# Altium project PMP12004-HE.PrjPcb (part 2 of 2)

## Sheet PMP12004-HE_sh6.SchDoc: VCCINT Core Rail
size 431 x 279 mm; Date: Not shown in title block; ApprovedBy: Not shown in title block; CheckedBy: Not shown in title block; Author: Not shown in title block; CompanyName: Not shown in title block; Engineer: Not shown in title block; Organization: Not shown in title block; Address1: Not shown in title block; Address2: Not shown in title block; Address3: Not shown in title block; Address4: Not shown in title block; DocumentNumber: 6; Revision: Use project parameter SCH_Rev; SheetNumber: 6; SheetTotal: 7; PageSetup: Record=PageOptions¦CenterHorizontal=True¦CenterVertical=True¦PrintScale=0.64¦XCorrection=1.00¦YCorrection=1.00¦PrintKind=0¦BorderSize=5000000¦LeftOffset=0¦BottomOffset=0¦Orientation=2¦PaperLength=1000¦PaperWidth=1000¦Scale=100¦PaperSource=15¦PrintQuality=600¦MediaType=1¦DitherType=10¦PrintScaleMode=1¦PaperKind=Letter
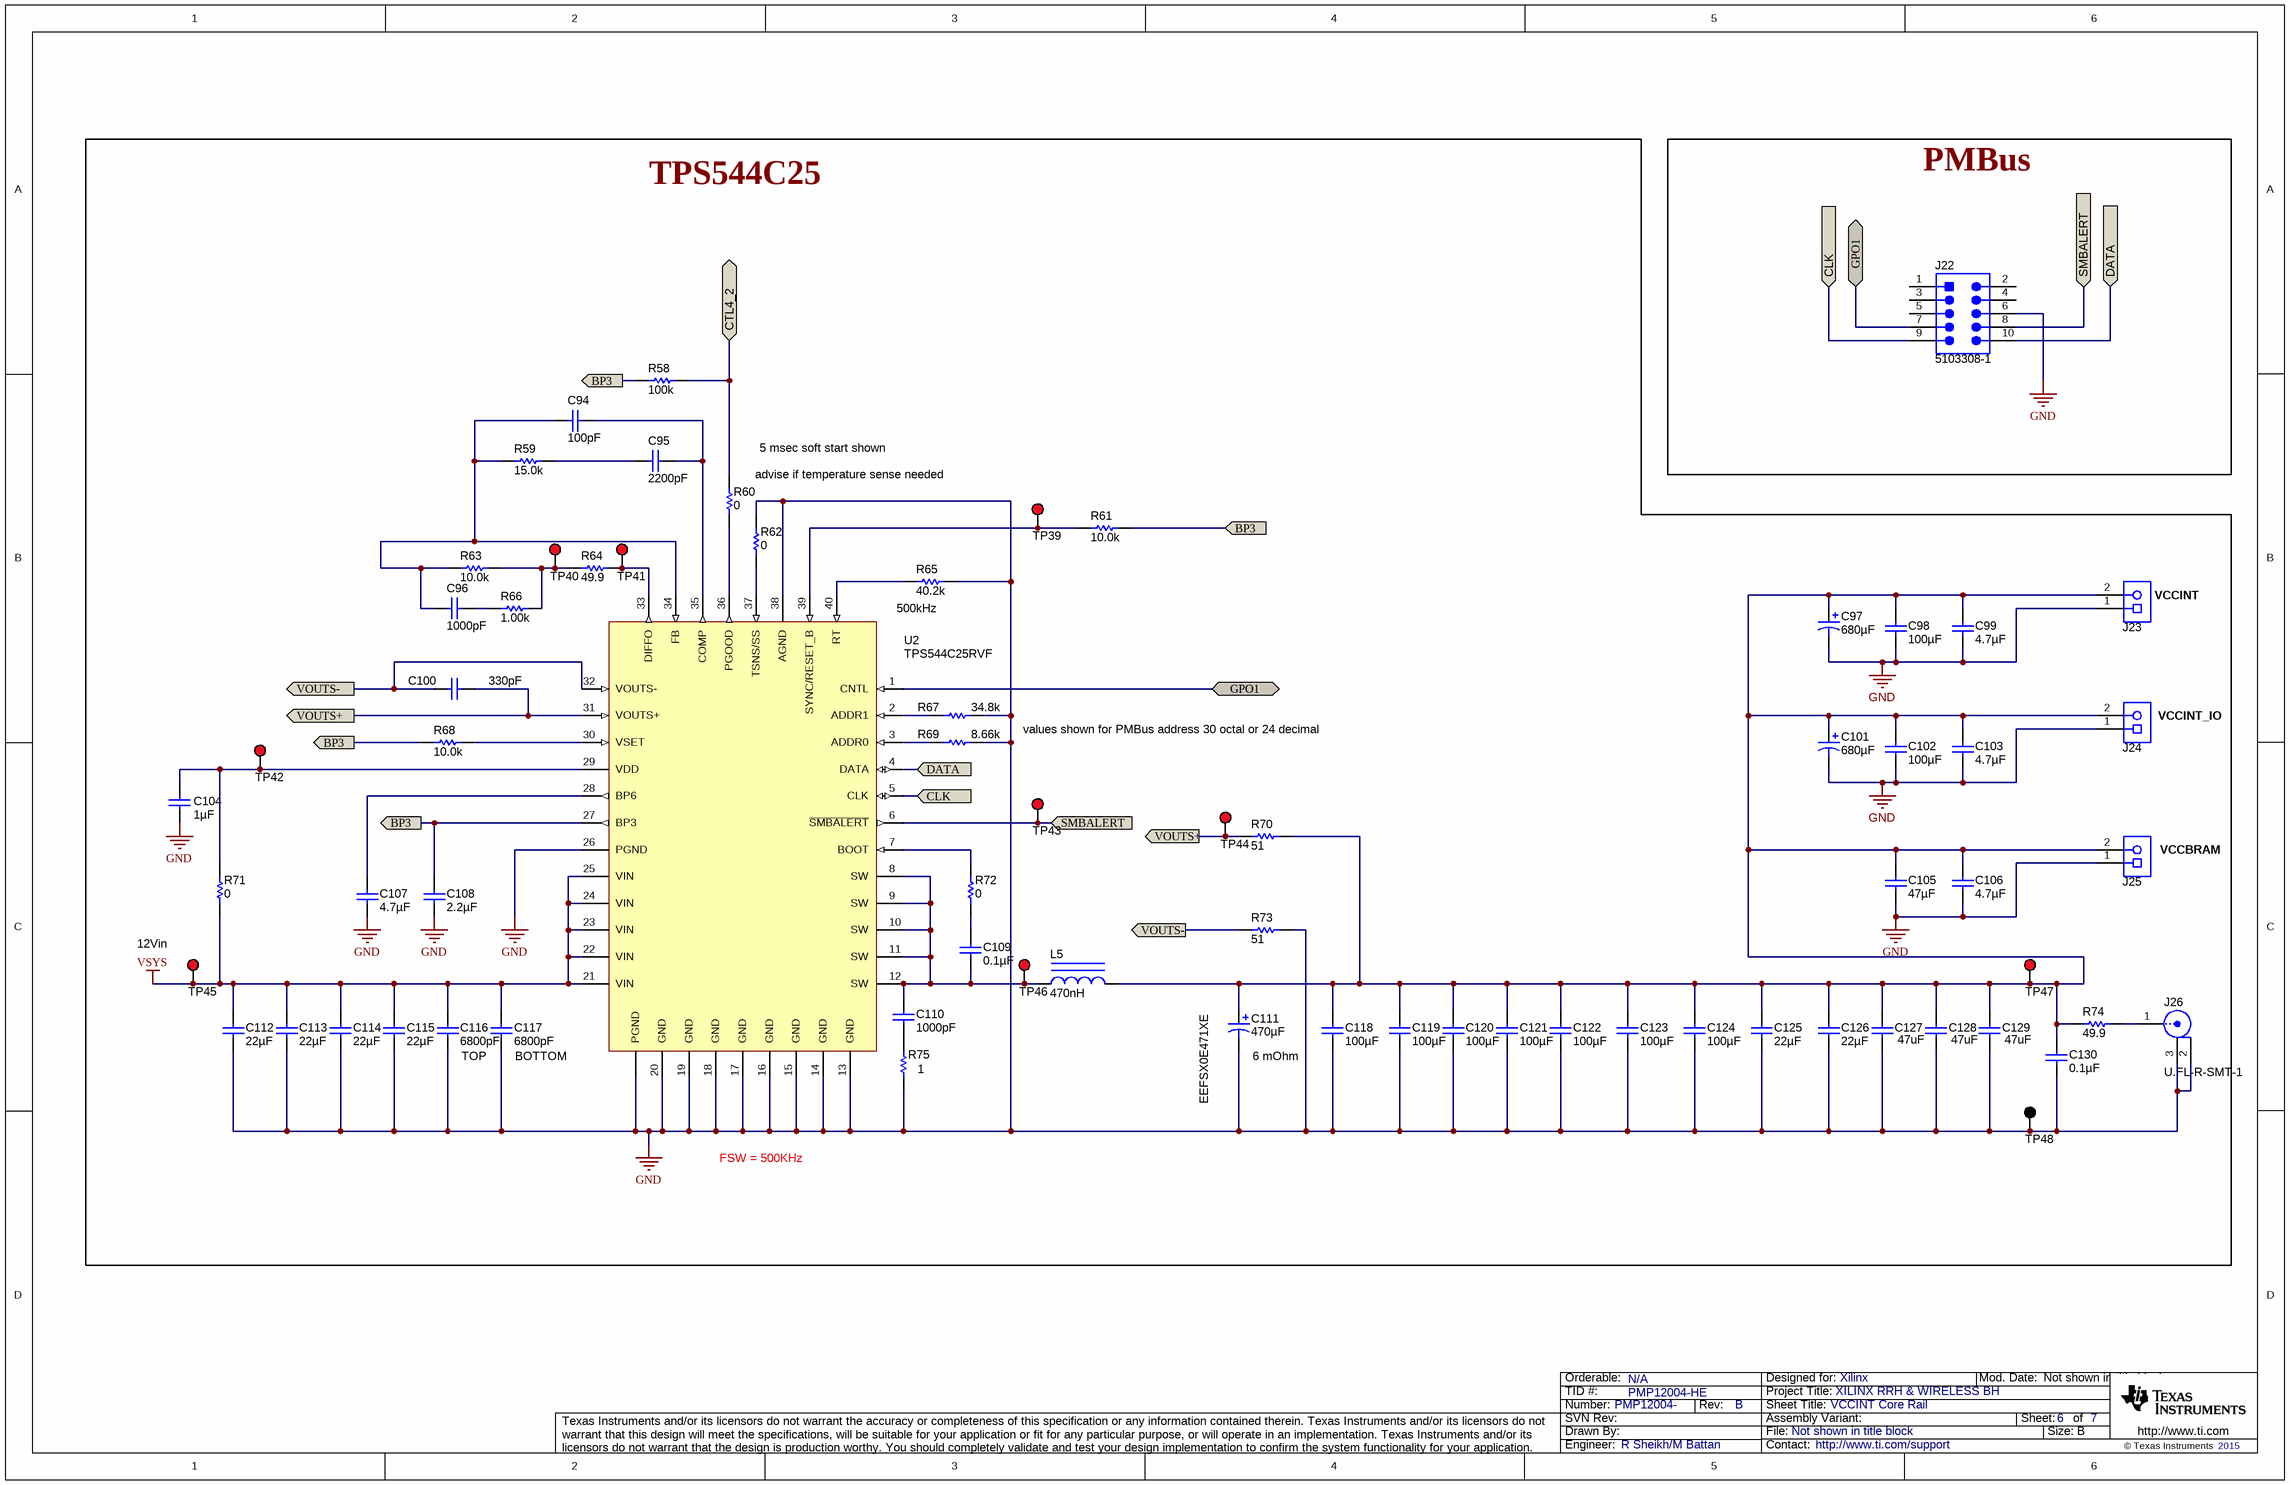
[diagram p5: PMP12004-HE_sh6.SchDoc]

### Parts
C94  ValueDisplayed: 100pF  [0402]  (hidden comment: GRM1535C1H101JDD5D)
C95  ValueDisplayed: 2200pF  [0402]  (hidden comment: C1005X7R1H222K)
C96  ValueDisplayed: 1000pF  [0402]  (hidden comment: GRM155R71H102KA01D)
C97  ValueDisplayed: 680µF  [SM_RADIAL_10AMM]  (hidden comment: 4SVP680M)
C98  ValueDisplayed: 100µF  [0805_HV]  (hidden comment: GRM21BR60G107ME15L)
C99  ValueDisplayed: 4.7µF  [0603]  (hidden comment: GRM188R60J475ME19D)
C100  ValueDisplayed: 330pF  [0402]  (hidden comment: GRM155R71H331KA01D)
C101  ValueDisplayed: 680µF  [SM_RADIAL_10AMM]  (hidden comment: 4SVP680M)
C102  ValueDisplayed: 100µF  [0805_HV]  (hidden comment: GRM21BR60G107ME15L)
C103  ValueDisplayed: 4.7µF  [0603]  (hidden comment: GRM188R60J475ME19D)
C104  ValueDisplayed: 1µF  [0603L]  (hidden comment: GRM188R71E105KA12D)
C105  ValueDisplayed: 47µF  [0603]  (hidden comment: GRM188R60J476M)
C106  ValueDisplayed: 4.7µF  [0603]  (hidden comment: GRM188R60J475KE19D)
C107  ValueDisplayed: 4.7µF  [0603]  (hidden comment: GRM185C81A475ME11D)
C108  ValueDisplayed: 2.2µF  [0402L]  (hidden comment: GRM155C80J225KE95D)
C109  ValueDisplayed: 0.1µF  [0402]  (hidden comment: C1005X7R1H104M)
C110  ValueDisplayed: 1000pF  [0603]  (hidden comment: 06031C102JAT2A)
C111  ValueDisplayed: 470µF  Value1: 6 mOhm  [SP-Cap_Standard]  (hidden comment: EEFSX0E471XE)
C112  ValueDisplayed: 22µF  [1210]  (hidden comment: GRM32EC81E226KE15L)
C113  ValueDisplayed: 22µF  [1210]  (hidden comment: GRM32EC81E226KE15L)
C114  ValueDisplayed: 22µF  [1210]  (hidden comment: GRM32EC81E226KE15L)
C115  ValueDisplayed: 22µF  [1210]  (hidden comment: GRM32EC81E226KE15L)
C116  ValueDisplayed: 6800pF  Placement: TOP  [0402]  (hidden comment: GRM155R71E682KA01D)
C117  ValueDisplayed: 6800pF  Placement: BOTTOM  [0402]  (hidden comment: GRM155R71E682KA01D)
C118  ValueDisplayed: 100µF  [1210]  (hidden comment: GRM32EC80J107ME20L)
C119  ValueDisplayed: 100µF  [1210]  (hidden comment: GRM32EC80J107ME20L)
C120  ValueDisplayed: 100µF  [1210]  (hidden comment: GRM32EC80J107ME20L)
C121  ValueDisplayed: 100µF  [1210]  (hidden comment: GRM32EC80J107ME20L)
C122  ValueDisplayed: 100µF  [1210]  (hidden comment: GRM32EC80J107ME20L)
C123  ValueDisplayed: 100µF  [1210]  (hidden comment: GRM32EC80J107ME20L)
C124  ValueDisplayed: 100µF  [1210]  (hidden comment: GRM32EC80J107ME20L)
C125  ValueDisplayed: 22µF  [0805_HV]  (hidden comment: GRM21BC80G226ME39L)
C126  ValueDisplayed: 22µF  [0805_HV]  (hidden comment: GRM21BC80G226ME39L)
C127  value 47uF  [0805_HV]  (hidden comment: GRM21BR61A476ME15)
C128  value 47uF  [0805_HV]  (hidden comment: GRM21BR61A476ME15)
C129  value 47uF  [0805_HV]  (hidden comment: GRM21BR61A476ME15)
C130  ValueDisplayed: 0.1µF  [0402]  (hidden comment: GRM155R61E104KA87D)
J22  5103308-1  [CONN_5103308-1]
J23  1935776  [Phoenix_1935776]  (value not drawn)
J24  1935776  [Phoenix_1935776]  (value not drawn)
J25  1935776  [Phoenix_1935776]  (value not drawn)
J26  U.FL-R-SMT-1  [CONN_UFL-R-SMT-1]
L5  ValueDisplayed: 470nH  [WE-HCM_1390]  (hidden comment: 744309047)
R58  ValueDisplayed: 100k  [0402]  (hidden comment: CRCW0402100KFKED)
R59  ValueDisplayed: 15.0k  [0402]  (hidden comment: CRCW040215K0FKED)
R60  ValueDisplayed: 0  [0402]  (hidden comment: CRCW04020000Z0ED)
R61  ValueDisplayed: 10.0k  [0402]  (hidden comment: CRCW040210K0FKED)
R62  ValueDisplayed: 0  [0402]  (hidden comment: CRCW04020000Z0ED)
R63  ValueDisplayed: 10.0k  [0402]  (hidden comment: CRCW040210K0FKED)
R64  ValueDisplayed: 49.9  [0402]  (hidden comment: ERJ-2RKF49R9X)
R65  ValueDisplayed: 40.2k  [0402]  (hidden comment: CRCW040240K2FKED)
R66  ValueDisplayed: 1.00k  [0402]  (hidden comment: CRCW04021K00FKED)
R67  ValueDisplayed: 34.8k  [0402]  (hidden comment: CRCW040234K8FKED)
R68  ValueDisplayed: 10.0k  [0402]  (hidden comment: CRCW040210K0FKED)
R69  ValueDisplayed: 8.66k  [0402]  (hidden comment: CRCW04028K66FKED)
R70  ValueDisplayed: 51  [0402]  (hidden comment: CRCW040251R0JNED)
R71  ValueDisplayed: 0  [0402]  (hidden comment: CRCW04020000Z0ED)
R72  ValueDisplayed: 0  [0402]  (hidden comment: CRCW04020000Z0ED)
R73  ValueDisplayed: 51  [0402]  (hidden comment: CRCW040251R0JNED)
R74  ValueDisplayed: 49.9  [0402]  (hidden comment: CRCW040249R9FKED)
R75  value 1  [1206]  (hidden comment: CRCW12061R00JNEA)
TP39  5000  [Keystone5000]  (value not drawn)
TP40  5000  [Keystone5000]  (value not drawn)
TP41  5000  [Keystone5000]  (value not drawn)
TP42  5000  [Keystone5000]  (value not drawn)
TP43  5000  [Keystone5000]  (value not drawn)
TP44  5000  [Keystone5000]  (value not drawn)
TP45  5000  [Keystone5000]  (value not drawn)
TP46  5000  [Keystone5000]  (value not drawn)
TP47  5000  [Keystone5000]  (value not drawn)
TP48  5001  [Keystone5001]  (value not drawn)
U2  TPS544C25RVF  [RVF0040A]

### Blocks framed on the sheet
TPS544C25: C94-C130 J23-J26 L5 R58-R75 TP39-TP48 U2
PMBus: J22

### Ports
BP3, CLK, CTL4_2 (bidir), DATA, GPO1 (bidir), SMBALERT, VOUTS+, VOUTS-

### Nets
GND: C97.2(-) C98.2 C99.2 C101.2(-) C102.2 C103.2 C104.2 C105.2 C106.2 C107.2 C108.2 C111.2(-) C112.2 C113.2 C114.2 C115.2 C116.2 C117.2 C118.2 C119.2 C120.2 C121.2 C122.2 C123.2 C124.2 C125.2 C126.2 C127.2 C128.2 C129.2 C130.2 J22.6 J23.1 J24.1 J25.1 J26.2 J26.3 R62.2 R65.2 R67.2 R69.2 R73.2 R75.1 TP48.1 U2.13(GND) U2.14(GND) U2.15(GND) U2.16(GND) U2.17(GND) U2.18(GND) U2.19(GND) U2.20(GND) U2.26(PGND) U2.38(AGND) U2.41(PGND)
VSYS: C112.1 C113.1 C114.1 C115.1 C116.1 C117.1 R71.1 TP45.1 U2.21(VIN) U2.22(VIN) U2.23(VIN) U2.24(VIN) U2.25(VIN)
BP3: C108.1 R58.1 R61.2 R68.1 U2.27(BP3) ; port BP3
CLK: J22.9 U2.5(CLK) ; port CLK
CTL4_2: R58.2 R60.1 ; port CTL4_2
DATA: J22.10 U2.4(DATA) ; port DATA
GPO1: J22.7 U2.1(CNTL) ; port GPO1
SMBALERT: J22.8 TP43.1 U2.6(~{SMBALERT}) ; port SMBALERT
VOUTS+: C100.1 R70.1 TP44.1 U2.31(VOUTS+) ; port VOUTS+
VOUTS-: C100.2 R73.1 U2.32(VOUTS-) ; port VOUTS-
NetC94_1: C94.1 C96.2 R59.1 R63.2 U2.34(FB)
NetC94_2: C94.2 C95.1 U2.35(COMP)
NetC95_2: C95.2 R59.2
NetC96_1: C96.1 R66.1
NetC97_1: C97.1(+) C98.1 C99.1 C101.1(+) C102.1 C103.1 C105.1 C106.1 C111.1(+) C118.1 C119.1 C120.1 C121.1 C122.1 C123.1 C124.1 C125.1 C126.1 C127.1 C128.1 C129.1 C130.1 J23.2 J24.2 J25.2 L5.2 R70.2 R74.1 TP47.1
NetC104_1: C104.1 R71.2 TP42.1 U2.29(VDD)
NetC107_1: C107.1 U2.28(BP6)
NetC109_1: C109.1 R72.1
NetC109_2: C109.2 C110.1 L5.1 TP46.1 U2.8(SW) U2.9(SW) U2.10(SW) U2.11(SW) U2.12(SW)
NetC110_2: C110.2 R75.2
NetJ26_1: J26.1 R74.2
NetR60_2: R60.2 U2.36(PGOOD)
NetR61_1: R61.1 TP39.1 U2.39(SYNC/RESET_B)
NetR62_1: R62.1 U2.37(TSNS/SS)
NetR63_1: R63.1 R64.1 R66.2 TP40.1
NetR64_2: R64.2 TP41.1 U2.33(DIFFO)
NetR65_1: R65.1 U2.40(RT)
NetR67_1: R67.1 U2.2(ADDR1)
NetR68_2: R68.2 U2.30(VSET)
NetR69_1: R69.1 U2.3(ADDR0)
NetR72_2: R72.2 U2.7(BOOT)

Not connected (* = marked no-connect by the designer): J22 1 2 3 4 5

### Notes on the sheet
- (near R60) 5 msec soft start shown
- (near R60) advise if temperature sense needed
- 500kHz
- (near J23) VCCINT
- values shown for PMBus address 30 octal or 24 decimal
- (near J24) VCCINT_IO
- (near J25) VCCBRAM
- (near TP45) 12Vin
- FSW = 500KHz

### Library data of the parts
C94 = GRM1535C1H101JDD5D: CAP, CERM, 100 pF, 50 V, +/- 5%, C0G/NP0, 0402; Manufacturer: MuRata; Polarized: N; CompType: Capacitor; Value: 100pF; U/M: EA; Cap_F: 0.0000000001; Tolerance_%: 5; Value1: Unknown; VDC_V: 50; Value2: 50V; TaMin_C: -55; TaMax_C: 125; AEC Category: Q200
C95 = C1005X7R1H222K: CAP, CERM, 2200 pF, 50 V, +/- 10%, X7R, 0402; Manufacturer: TDK; Polarized: N; CompType: Capacitor; Value: 2200pF; U/M: EA; Cap_F: 0.0000000022; Tolerance_%: 10; ESR_ohm: 0.1433; Value1: 0.1433 ohm; VDC_V: 50; Value2: 50V; TaMin_C: -55; TaMax_C: 125; AEC Category: Q200
C96 = GRM155R71H102KA01D: CAP, CERM, 1000 pF, 50 V, +/- 10%, X7R, 0402; Manufacturer: MuRata; Polarized: N; CompType: Capacitor; Value: 1000pF; U/M: EA; Cap_F: 0.000000001; Tolerance_%: 10; Value1: Unknown; VDC_V: 50; Value2: 50V; TaMin_C: -55; TaMax_C: 125; AEC Category: Q200
C97 C101 = 4SVP680M: CAP, Aluminum Polymer, 680 µF, 4 V, +/- 20%, 0.025 ohm, 10x10.3 SMD; Manufacturer: Panasonic; Polarized: Y; CompType: Capacitor; Value: 680uF; U/M: EA; Cap_F: 0.00068; Tolerance_%: 20; VDC_V: 4; Value2: 4V; ESR_ohm: 0.025; IRMS_A: 3.7; TaMin_C: -55; TaMax_C: 105; Cap_Case: 10.3x10.3x7.9; AEC Category: Q200
C98 C102 = GRM21BR60G107ME15L: CAP, CERM, 100 µF, 4 V, +/- 20%, X5R, 0805; Manufacturer: MuRata; Polarized: N; CompType: Capacitor; Value: 100uF; U/M: EA; Cap_F: 0.0001; Tolerance_%: 20; Value1: Unknown; VDC_V: 4; Value2: 4V; TaMin_C: -55; TaMax_C: 85; Cap_Case: 0805; AEC Category: Q200
C99 C103 = GRM188R60J475ME19D: CAP, CERM, 4.7 µF, 6.3 V, +/- 20%, X5R, 0603; Manufacturer: MuRata; Polarized: N; CompType: Capacitor; Value: 4.7uF; U/M: EA; Cap_F: 0.0000047; Tolerance_%: 20; ESR_ohm: 0.001; Value1: 0.001 ohm; VDC_V: 6.3; Value2: 6.3V; TaMin_C: -55; TaMax_C: 125; AEC Category: Q200
C100 = GRM155R71H331KA01D: CAP, CERM, 330 pF, 50 V, +/- 10%, X7R, 0402; Manufacturer: MuRata; Polarized: N; CompType: Capacitor; Value: 330pF; U/M: EA; Cap_F: 0.00000000033; Tolerance_%: 10; Value1: Unknown; VDC_V: 50; Value2: 50V; TaMin_C: -55; TaMax_C: 125
C104 = GRM188R71E105KA12D: CAP, CERM, 1uF, 25V, +/-10%, X7R, 0603; Manufacturer: MuRata; Polarized: N; CompType: Capacitor; U/M: EA; Cap_F: 0.000001; Tolerance_%: 10; Value1: Unknown; VDC_V: 25; TaMin_C: -55; TaMax_C: 125; Cap_Case: 0603
C105 = GRM188R60J476M: CAP, CERM, 47 µF, 6.3 V, +/- 20%, X5R, 0603; Manufacturer: MuRata; Polarized: N; CompType: Capacitor; Value: 47uF; U/M: EA; Cap_F: 0.000047; Tolerance_%: 20; Value1: Unknown; VDC_V: 6.3; Value2: 6.3V; TaMin_C: -55; TaMax_C: 85; AEC Category: Q200
C106 = GRM188R60J475KE19D: CAP, CERM, 4.7 µF, 6.3 V, +/- 10%, X5R, 0603; Manufacturer: MuRata; Polarized: N; CompType: Capacitor; Value: 4.7uF; U/M: EA; Cap_F: 0.0000047; Tolerance_%: 10; ESR_ohm: 0.005; Value1: 0.005 ohm; VDC_V: 6.3; Value2: 6.3V; IRMS_A: 2; TaMin_C: -55; TaMax_C: 85; AEC Category: Q200
C107 = GRM185C81A475ME11D: CAP, CERM, 4.7 µF, 10 V, +/- 20%, X6S, 0603; Manufacturer: MuRata; Polarized: N; CompType: Capacitor; Value: 4.7uF; U/M: EA; Cap_F: 0.0000047; Tolerance_%: 20; Value1: Unknown; VDC_V: 10; Value2: 10V; TaMin_C: -55; TaMax_C: 105
C108 = GRM155C80J225KE95D: CAP, CERM, 2.2 µF, 6.3 V, +/- 10%, X6S, 0402; Manufacturer: MuRata; Polarized: N; CompType: Capacitor; Value: 2.2uF; U/M: EA; Cap_F: 0.0000022; Tolerance_%: 10; Value1: Unknown; VDC_V: 6.3; Value2: 6.3V; TaMin_C: -55; TaMax_C: 105; Cap_Case: 0402
C109 = C1005X7R1H104M: CAP, CERM, 0.1 µF, 50 V, +/- 20%, X7R, 0402; Manufacturer: TDK; Polarized: N; CompType: Capacitor; Value: 0.1uF; U/M: EA; Cap_F: 0.0000001; Tolerance_%: 20; Value1: Unknown; VDC_V: 50; Value2: 50V; TaMin_C: -55; TaMax_C: 125
C110 = 06031C102JAT2A: CAP, CERM, 1000pF, 100V, +/-5%, X7R, 0603; Manufacturer: AVX; Polarized: N; CompType: Capacitor; U/M: EA; Cap_F: 0.000000001; Tolerance_%: 5; ESR_Ohm: 0.276; Value1: 0.276 ohm; VDC_V: 100; TaMin_C: -55; TaMax_C: 125
C111 = EEFSX0E471ER: CAP, Aluminum Polymer, 470 µF, 2.5 V, +/- 20%, 9 ohm, 7.3x1.8x4.3mm SMD; Manufacturer: Panasonic; Polarized: Y; CompType: Capacitor; Value: 470uF; U/M: EA; Cap_F: 0.00047; Tolerance_%: 20; VDC_V: 2.5; Value2: 2.5V; ESR_ohm: 9; IRMS_A: 3; TaMin_C: -40; TaMax_C: 105
C112-C115 = GRM32EC81E226KE15L: CAP, CERM, 22uF, 25V, +/-10%, X6S, 1210; Manufacturer: MuRata; Polarized: N; CompType: Capacitor; U/M: EA; Cap_F: 0.000022; Tolerance_%: 10; Value1: Unknown; VDC_V: 25; TaMin_C: -55; TaMax_C: 105
C116 C117 = GRM155R71E682KA01D: CAP, CERM, 6800pF, 25V, +/-10%, X7R, 0402; Manufacturer: MuRata; Polarized: N; CompType: Capacitor; U/M: EA; Cap_F: 0.0000000068; Tolerance_%: 10; Value1: Unknown; VDC_V: 25; TaMin_C: -55; TaMax_C: 125
C118-C124 = GRM32EC80J107ME20L: CAP, CERM, 100 µF, 6.3 V, +/- 20%, X6S, 1210; Manufacturer: MuRata; Polarized: N; CompType: Capacitor; Value: 100uF; U/M: EA; Cap_F: 0.0001; Tolerance_%: 20; Value1: Unknown; VDC_V: 6.3; Value2: 6.3V; TaMin_C: -55; TaMax_C: 105
C125 C126 = GRM21BC80G226ME39L: CAP, CERM, 22 µF, 4 V, +/- 20%, X6S, 0805; Manufacturer: MuRata; Polarized: N; CompType: Capacitor; Value: 22uF; U/M: EA; Cap_F: 0.000022; Tolerance_%: 20; Value1: Unknown; VDC_V: 4; Value2: 4V; TaMin_C: -55; TaMax_C: 105; Cap_Case: 0805
C127-C129 = GRM21BR61A476ME15: CAP, CERM, 47 µF, 10 V, +/- 20%, X5R, 0805; Manufacturer: MuRata; Polarized: N; CompType: Capacitor; ValueDisplayed: DNP; U/M: EA; Cap_F: 0.000047; Tolerance_%: 20; Value1: Unknown; VDC_V: 10; Value2: 10V; TaMin_C: -55; TaMax_C: 85; Cap_Case: 0805; AEC Category: Q200
C130 = GRM155R61E104KA87D: CAP, CERM, 0.1 µF, 25 V, +/- 10%, X5R, 0402; Manufacturer: MuRata; Polarized: N; CompType: Capacitor; Value: 0.1uF; U/M: EA; Cap_F: 0.0000001; Tolerance_%: 10; Value1: Unknown; VDC_V: 25; Value2: 25V; TaMin_C: -55; TaMax_C: 85
J22 = 5103308-1: Header (shrouded), 100mil, 5x2, Gold, TH; Manufacturer: TE Connectivity; SymbolCreator: a0412235; U/M: EA
J23-J25 = 1935776: Terminal Block, 2x1, 5mm, Green, TH; Manufacturer: Phoenix Contact; SymbolCreator: a0412235; U/M: EA
J26 = U.FL-R-SMT-1: Connector, Ultra-Mini Coaxial, SMD; Manufacturer: Hirose Electric Co. Ltd.; SymbolCreator: a0412235; U/M: EA
L5 = 744309047: Inductor, Shielded Drum Core, Ferrite, 470 nH, 40.5 A, 0.000165 ohm, SMD; Manufacturer: Wurth Elektronik; Value: 470nH; Ind_H: 470.0E-9; Imax_A: 40.5; Irms: 47.5A @ 40C rise; Isat: 40.5A @ 20% inductance drop; Value2: 40.5A; AEC Category: Q200
R58 = CRCW0402100KFKED: RES, 100 k, 1%, 0.063 W, 0402; Manufacturer: Vishay-Dale; CompType: Resistor; Value: 100k; Res_ohm: 100000; Tolerance_%: 1; Power_W: 0.063; Value2: 0.063W; VDC_V: 50; TempCo: 100 ppm/C; EIA_Code: E96; U/M: EA
R59 = CRCW040215K0FKED: RES, 15.0 k, 1%, 0.063 W, 0402; Manufacturer: Vishay-Dale; CompType: Resistor; Value: 15.0k; Res_ohm: 15000; Value_Code: 15k0; Tolerance_%: 1; Power_W: 0.063; Value2: 0.063W; VDC_V: 50; TempCo: 100 ppm/C; EIA_Code: E96; U/M: EA; AEC Category: Q200
R60 R62 R71 R72 = CRCW04020000Z0ED: RES, 0, 5%, 0.063 W, 0402; Manufacturer: Vishay-Dale; CompType: Resistor; Value: 0; Value_Code: 0000; Tolerance_%: 5; Power_W: 0.063; Value2: 0.063W; VDC_V: 50; TempCo: 200 ppm/C; EIA_Code: E24; U/M: EA
R61 R63 R68 = CRCW040210K0FKED: RES, 10.0 k, 1%, 0.063 W, 0402; Manufacturer: Vishay-Dale; CompType: Resistor; Value: 10.0k; Res_ohm: 10000; Value_Code: 10k0; Tolerance_%: 1; Power_W: 0.063; Value2: 0.063W; VDC_V: 50; TempCo: 100 ppm/C; EIA_Code: E96; U/M: EA
R64 = ERJ-2RKF49R9X: RES, 49.9, 1%, 0.1 W, AEC-Q200 Grade 0, 0402; Manufacturer: Panasonic; CompType: Resistor; Value: 49.9; Value_Code: 49R9; Tolerance_%: 1; Power_W: 0.1; Value2: 0.1W; VDC_V: 50; TempCo: 100 ppm/C; EIA_Code: E96; U/M: EA; AEC Category: Q200; AEC Qualified: Y; AEC Grade: 0
R65 = CRCW040240K2FKED: RES, 40.2 k, 1%, 0.063 W, 0402; Manufacturer: Vishay-Dale; CompType: Resistor; Value: 40.2k; Res_ohm: 40200; Value_Code: 40k2; Tolerance_%: 1; Power_W: 0.063; Value2: 0.063W; VDC_V: 50; TempCo: 100 ppm/C; EIA_Code: E96; U/M: EA
R66 = CRCW04021K00FKED: RES, 1.00 k, 1%, 0.063 W, 0402; Manufacturer: Vishay-Dale; CompType: Resistor; Value: 1.00k; Res_ohm: 1000; Value_Code: 1k00; Tolerance_%: 1; Power_W: 0.063; Value2: 0.063W; VDC_V: 50; TempCo: 100 ppm/C; EIA_Code: E96; U/M: EA
R67 = CRCW040234K8FKED: RES, 34.8 k, 1%, 0.063 W, 0402; Manufacturer: Vishay-Dale; CompType: Resistor; Value: 34.8k; Res_ohm: 34800; Value_Code: 34k8; Tolerance_%: 1; Power_W: 0.063; Value2: 0.063W; VDC_V: 50; TempCo: 100 ppm/C; EIA_Code: E96; U/M: EA
R69 = CRCW04028K66FKED: RES, 8.66 k, 1%, 0.063 W, 0402; Manufacturer: Vishay-Dale; CompType: Resistor; Value: 8.66k; Res_ohm: 8660; Value_Code: 8k66; Tolerance_%: 1; Power_W: 0.063; Value2: 0.063W; VDC_V: 50; TempCo: 100 ppm/C; EIA_Code: E96; U/M: EA
R70 R73 = CRCW040251R0JNED: RES, 51, 5%, 0.063 W, 0402; Manufacturer: Vishay-Dale; CompType: Resistor; Value: 51; Value_Code: 51R0; Tolerance_%: 5; Power_W: 0.063; Value2: 0.063W; VDC_V: 50; TempCo: 200 ppm/C; EIA_Code: E24; U/M: EA
R74 = CRCW040249R9FKED: RES, 49.9, 1%, 0.063 W, 0402; Manufacturer: Vishay-Dale; CompType: Resistor; Value: 49.9; Value_Code: 49R9; Tolerance_%: 1; Power_W: 0.063; Value2: 0.063W; VDC_V: 50; TempCo: 100 ppm/C; EIA_Code: E96; U/M: EA
R75 = CRCW12061R00JNEA: RES, 1.0 ohm, 5%, 0.25W, 1206; Manufacturer: Vishay-Dale; CompType: Resistor; Value_Code: 1R00; Tolerance_%: 5; Power_W: 0.25; VDC_V: 200; TempCo: 200 ppm/C; EIA_Code: E24; U/M: EA
TP39-TP47 = 5000: Test Point, Miniature, Red, TH; Manufacturer: Keystone; CompType: Test Point Loop; U/M: EA
TP48 = 5001: Test Point, Miniature, Black, TH; Manufacturer: Keystone; CompType: Test Point Loop; U/M: EA
U2 = TPS544C24RVF: 18V, 30A PMBUS SYNCHRONOUS BUCK CONVERTERS, RVF0040A; Alternate Manufacturer: None; Manufacturer: Texas Instruments; SymbolCreator: a0411947; CompType: IC; U/M: EA

## Sheet PMP12004-HE_Hardware.SchDoc
size 431 x 279 mm; Date: Not shown in title block; ApprovedBy: Not shown in title block; CheckedBy: Not shown in title block; Author: Not shown in title block; CompanyName: Not shown in title block; Engineer: Not shown in title block; Organization: Not shown in title block; Address1: Not shown in title block; Address2: Not shown in title block; Address3: Not shown in title block; Address4: Not shown in title block; DocumentNumber: 7; Revision: Use project parameter SCH_Rev; SheetNumber: 7; SheetTotal: 7; PageSetup: Record=PageOptions¦CenterHorizontal=True¦CenterVertical=True¦PrintScale=1.00¦XCorrection=1.00¦YCorrection=1.00¦PrintKind=0¦BorderSize=5000000¦LeftOffset=0¦BottomOffset=0¦Orientation=2¦PaperLength=1000¦PaperWidth=1000¦Scale=100¦PaperSource=15¦PrintQuality=600¦MediaType=1¦DitherType=10¦PaperKind=Letter¦PrintScaleMode=1
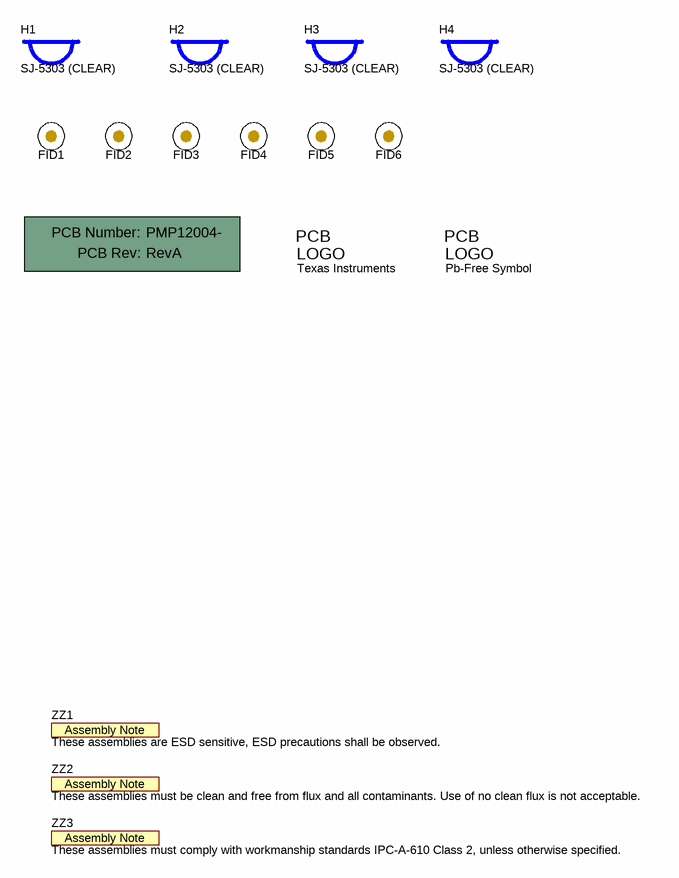
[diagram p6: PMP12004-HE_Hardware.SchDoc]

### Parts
!PCB1  Printed Circuit Board  (value not drawn)  (mechanical)
FID1  Fiducial  [Fiducial10-20]  (value not drawn)  (no BOM)
FID2  Fiducial  [Fiducial10-20]  (value not drawn)  (no BOM)
FID3  Fiducial  [Fiducial10-20]  (value not drawn)  (no BOM)
FID4  Fiducial  [Fiducial10-20]  (value not drawn)  (no BOM)
FID5  Fiducial  [Fiducial10-20]  (value not drawn)  (no BOM)
FID6  Fiducial  [Fiducial10-20]  (value not drawn)  (no BOM)
H1  SJ-5303 (CLEAR)  [Bumpon_SJ5003Transparent]
H2  SJ-5303 (CLEAR)  [Bumpon_SJ5003Transparent]
H3  SJ-5303 (CLEAR)  [Bumpon_SJ5003Transparent]
H4  SJ-5303 (CLEAR)  [Bumpon_SJ5003Transparent]
Logo1  Texas Instruments  [TI_Stacked_Overlay_Small]  (no BOM)
Logo2  Pb-Free Symbol  [Pb-Free_Overlay_Small]  (no BOM)
ZZ1  These assemblies are ESD sensitive, ESD precautions shall be observed.  [AssemblyNote]  (no BOM)
ZZ2  These assemblies must be clean and free from flux and all contaminants. Use of no clean flux is not acceptable.  [AssemblyNote]  (no BOM)
ZZ3  These assemblies must comply with workmanship standards IPC-A-610 Class 2, unless otherwise specified.  [AssemblyNote]  (no BOM)

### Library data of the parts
!PCB1 = PCB: Manufacturer: Any; PartNumber: PMP12004-; SymbolCreator: a0412235
FID1-FID6 = Fiducial: Fiducial mark.  There is nothing to buy or mount.; SymbolCreator: codlsc
H1-H4 = SJ-5303 (CLEAR): Bumpon, Hemisphere, 0.44 X 0.20, Clear; Manufacturer: 3M; SymbolCreator: a0412235
Logo1 = TI_Logo: Texas Instrument Corporate Signature; SymbolCreator: codlsc
Logo2 = Pb-Free: SymbolCreator: a0412235
ZZ1-ZZ3 = AssemblyNote: SymbolCreator: codlsc

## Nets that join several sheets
BUCK1_OUT: PMP12004-HE_sh1 (5 pins), PMP12004-HE_sh2 (16 pins)
BUCK5_OUT: PMP12004-HE_sh1 (R1.1 R3.1), PMP12004-HE_sh4 (19 pins)
BUCK6_OUT: PMP12004-HE_sh1 (R7.1), PMP12004-HE_sh4 (18 pins)
GND: PMP12004-HE_sh1 (31 pins), PMP12004-HE_sh2 (50 pins), PMP12004-HE_sh3 (60 pins), PMP12004-HE_sh4 (49 pins), PMP12004-HE_sh5 (19 pins), PMP12004-HE_sh6 (55 pins)
LDO3P3: PMP12004-HE_sh1 (9 pins), PMP12004-HE_sh3 (C143.1 C157.1 U3.10 U4.10), PMP12004-HE_sh5 (7 pins)
VSYS: PMP12004-HE_sh1 (C1.1 J1.2 R15.2 TP1.1), PMP12004-HE_sh2 (R21.1 R29.1), PMP12004-HE_sh4 (R42.1), PMP12004-HE_sh6 (13 pins)
BOOT1: PMP12004-HE_sh1 (U1.35), PMP12004-HE_sh2 (R20.1)
BOOT2: PMP12004-HE_sh1 (U1.5), PMP12004-HE_sh2 (R28.1)
BOOT6: PMP12004-HE_sh1 (U1.41), PMP12004-HE_sh4 (R41.1)
CTL4_2: PMP12004-HE_sh1 (R11.1 R12.1), PMP12004-HE_sh6 (R58.2 R60.1)
DRVH1: PMP12004-HE_sh1 (U1.33), PMP12004-HE_sh2 (R22.1)
DRVH2: PMP12004-HE_sh1 (U1.3), PMP12004-HE_sh2 (R30.1)
DRVH6: PMP12004-HE_sh1 (U1.43), PMP12004-HE_sh4 (R43.1)
DRVL1: PMP12004-HE_sh1 (U1.37), PMP12004-HE_sh2 (R23.1)
DRVL2: PMP12004-HE_sh1 (U1.7), PMP12004-HE_sh2 (R31.1)
DRVL6: PMP12004-HE_sh1 (U1.39), PMP12004-HE_sh4 (R44.1)
FB3: PMP12004-HE_sh1 (U1.12), PMP12004-HE_sh3 (R80.1)
FB4: PMP12004-HE_sh1 (U1.23), PMP12004-HE_sh3 (R85.1)
FB5: PMP12004-HE_sh1 (U1.22), PMP12004-HE_sh4 (R39.1)
FBGND2: PMP12004-HE_sh1 (U1.1), PMP12004-HE_sh2 (R35.1)
FBVOUT1: PMP12004-HE_sh1 (U1.29), PMP12004-HE_sh2 (R26.1)
FBVOUT2: PMP12004-HE_sh1 (U1.2), PMP12004-HE_sh2 (R34.1)
FBVOUT6: PMP12004-HE_sh1 (U1.44), PMP12004-HE_sh4 (R47.1)
GPO1: PMP12004-HE_sh1 (U1.16), PMP12004-HE_sh5 (R53.1), PMP12004-HE_sh6 (J22.7 U2.1)
GPO2: PMP12004-HE_sh1 (U1.26), PMP12004-HE_sh5 (R55.1)
GPO3: PMP12004-HE_sh1 (U1.27), PMP12004-HE_sh5 (R52.1)
GPO4: PMP12004-HE_sh1 (U1.28), PMP12004-HE_sh5 (R54.1)
ILIM1: PMP12004-HE_sh1 (U1.30), PMP12004-HE_sh2 (R27.1)
ILIM2: PMP12004-HE_sh1 (U1.64), PMP12004-HE_sh2 (R36.1)
ILIM6: PMP12004-HE_sh1 (U1.45), PMP12004-HE_sh4 (R49.1)
IRQB: PMP12004-HE_sh1 (U1.15), PMP12004-HE_sh5 (R51.1)
LDOA1: PMP12004-HE_sh1 (U1.9), PMP12004-HE_sh5 (C88.1 J15.2 TP27.1)
LDOA2: PMP12004-HE_sh1 (U1.51), PMP12004-HE_sh5 (C89.1 J16.2 TP28.1)
LDOA3: PMP12004-HE_sh1 (U1.49), PMP12004-HE_sh5 (C90.1 J17.2 TP29.1)
LX3: PMP12004-HE_sh1 (U1.10), PMP12004-HE_sh3 (L6.1)
LX4: PMP12004-HE_sh1 (U1.25), PMP12004-HE_sh3 (L7.1)
LX5: PMP12004-HE_sh1 (U1.20), PMP12004-HE_sh4 (L3.1)
SCL: PMP12004-HE_sh1 (U1.58), PMP12004-HE_sh5 (J21.9 R56.2)
SDA: PMP12004-HE_sh1 (U1.59), PMP12004-HE_sh5 (J21.10 R57.2)
SW1: PMP12004-HE_sh1 (U1.34), PMP12004-HE_sh2 (C18.1 Q1.4)
SW2: PMP12004-HE_sh1 (U1.4), PMP12004-HE_sh2 (C31.1 Q2.4)
SW6: PMP12004-HE_sh1 (U1.42), PMP12004-HE_sh4 (C71.1 Q3.4)
SWA1: PMP12004-HE_sh1 (U1.31), PMP12004-HE_sh5 (C93.1 J20.2 TP35.1)
SWB1: PMP12004-HE_sh1 (U1.17), PMP12004-HE_sh5 (C91.1 J18.2 R50.2 TP33.1)
SWB2: PMP12004-HE_sh1 (U1.19), PMP12004-HE_sh5 (C92.1 J19.2 R50.1 TP34.1)
VTT: PMP12004-HE_sh1 (U1.47), PMP12004-HE_sh4 (9 pins)
VTTFB: PMP12004-HE_sh1 (U1.48), PMP12004-HE_sh4 (R40.1)

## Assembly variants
001: not fitted C26 C27 C28 C30 C46 C47 C48 C50 C61 C62 C63 C81 C82 C83 C84 C85 C87 C127 C128 C129 C137 C138 C139 C140 C141 C152 C153 C154 C155 C156 R11 R19 R25 R32 R46 R50 R56 R57
001b: not fitted C26 C27 C28 C30 C46 C47 C48 C50 C81 C82 C83 C84 C85 C87 C127 C128 C129 C141 C156 R11 R19 R25 R32 R46 R50 R56 R57; alternate parts C140 -> GRM21BR61A476ME15, C155 -> GRM21BR61A476ME15
003: not fitted C26 C27 C28 C30 C46 C47 C48 C50 C81 C82 C83 C84 C85 C87 C127 C128 C129 C131 C132 C141 C143 C144 C145 C146 C156 C157 C158 C901 C902 C903 R11 R19 R25 R32 R46 R50 R56 R57 R76 R77 R79 R81 R83 R84 U3 U4; alternate parts C140 -> GRM21BR61A476ME15, C155 -> GRM21BR61A476ME15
